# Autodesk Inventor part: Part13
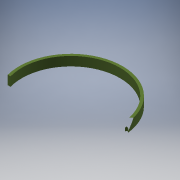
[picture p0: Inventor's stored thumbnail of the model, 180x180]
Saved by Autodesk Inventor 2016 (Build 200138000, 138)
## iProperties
Created: 2020-04
Part Number: Part13
Material: Generic
Document SubType Name: Modeling
Designer: merlin
Density: 1 g/cm^3
Appearance: Olive Green
Author: merlin
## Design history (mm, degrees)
sketch "Sketch1"
  geometry: L1 (115.887, 222.25)-(118.173, 222.25); A1 r 41.214 centre (76.2, 211.138) between (35.238, 206.586) and (115.887, 222.25); A2 r 43.419 centre (76.2, 211.138) between (33.047, 206.343) and (118.173, 222.25); A3 r 1.103 centre (34.142, 206.464) between (33.047, 206.343) and (35.238, 206.586); 1 further point
  constraints: 6 point on circle, 3 centre point, 2 end point, 2 tangent, 1 coincident, 1 horizontal
extrude "Extrusion1" new body sketch "Sketch1" distance "d0" = 7.62; taper "d1" = 0 deg
body "Solid1"
